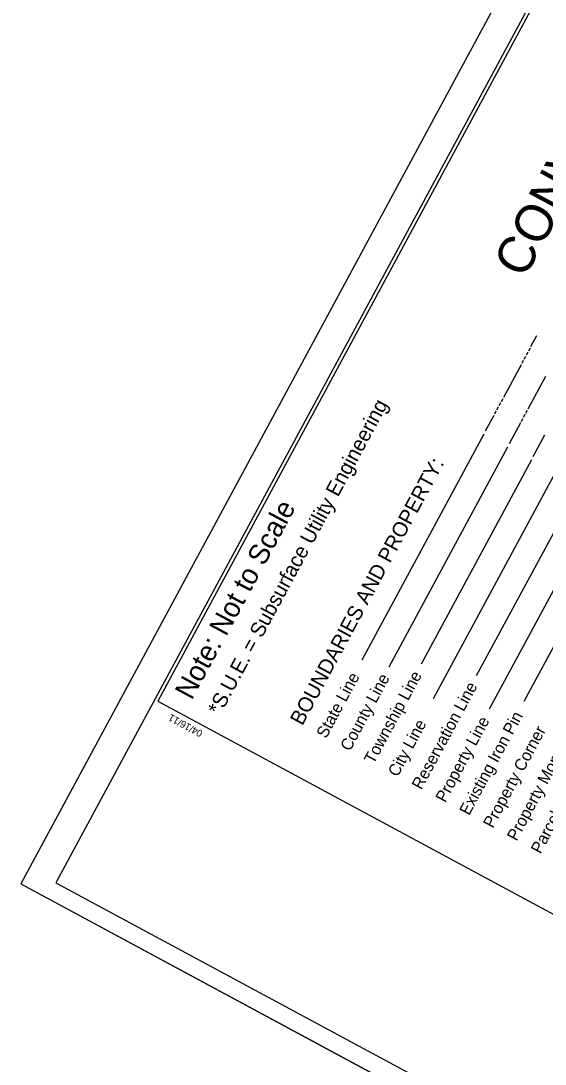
# Model space of a CAD drawing. Extents: x 1376167 to 1379209, y 761324 to 763997.
# Drawn here: x 1377442 to 1377829, y 761712 to 762484 of the extents above; entities that cross this region are included whole.
import ezdxf

# ---------------------------------------------------------------- set-up
doc = ezdxf.new("R2010")
doc.units = 0
for name, color, linetype in [('Sheet Cutting Line CELL', 7, 'Continuous'), ('Sheet Plot Border Inside CELL', 7, 'Continuous'), ('Sheet Plot Border Outside CELL', 7, 'Continuous'), ('Sheet Summary Guardrail CELL', 7, 'Continuous'), ('Sheet Symbology CELL', 7, 'Continuous')]:
    doc.layers.add(name, color=color, linetype=linetype)

msp = doc.modelspace()

# ---------------------------------------------------------------- linework, layer by layer
at = {"layer": 'Sheet Cutting Line CELL'}
for p, q in [((1378241.03, 763327.89), (1377441.9, 761845.58)), ((1377441.9, 761845.58), (1378410.15, 761323.58))]:
    msp.add_line(p, q, dxfattribs=at)
at = {"layer": 'Sheet Plot Border Inside CELL'}
msp.add_lwpolyline([(1378396.56, 761345.67), (1379187.39, 762812.58), (1378258.66, 763313.27), (1377467.83, 761846.37)], close=True, dxfattribs=at)
at = {"layer": 'Sheet Plot Border Outside CELL'}
msp.add_lwpolyline([(1378410.15, 761323.58), (1379209.29, 762805.89), (1378241.03, 763327.89), (1377441.9, 761845.58)], close=True, dxfattribs=at)
at = {"layer": 'Sheet Symbology CELL'}
for p, q in [((1377818.91, 762242.95), (1377823.33, 762251.13)), ((1377815.59, 762236.79), (1377816.78, 762238.99)), ((1377817.25, 762239.87), (1377818.44, 762242.07)), ((1377798.74, 762205.54), (1377811.79, 762229.75)), ((1377812.27, 762230.63), (1377813.45, 762232.83)), ((1377813.93, 762233.71), (1377815.12, 762235.91)), ((1377816.77, 762196.83), (1377829.82, 762221.04)), ((1377793.76, 762196.3), (1377794.95, 762198.5)), ((1377795.42, 762199.38), (1377796.61, 762201.58)), ((1377797.08, 762202.46), (1377798.27, 762204.66)), ((1377785.36, 762180.72), (1377791.63, 762192.34)), ((1377792.1, 762193.22), (1377793.29, 762195.42)), ((1377813.45, 762190.67), (1377814.63, 762192.87)), ((1377815.11, 762193.75), (1377816.3, 762195.95)), ((1377802.97, 762171.23), (1377811.31, 762186.71)), ((1377811.79, 762187.59), (1377812.97, 762189.79)), ((1377784, 762178.19), (1377693.84, 762010.95)), ((1377820.57, 762161.73), (1377829.14, 762177.62)), ((1377801.6, 762168.69), (1377713.81, 762005.85)), ((1377819.21, 762159.2), (1377737.73, 762008.07)), ((1377836.81, 762149.71), (1377746.65, 761982.48)), ((1377854.42, 762140.22), (1377778.45, 761999.32)), ((1377872.02, 762130.73), (1377787.91, 761974.72)), ((1377889.63, 762121.24), (1377813.66, 761980.34))]:
    msp.add_line(p, q, dxfattribs=at)
msp.add_lwpolyline([(1378254.97, 763301.06), (1377543.15, 761980.71), (1378466.5, 761482.92), (1379178.32, 762803.27)], close=True, dxfattribs=at)

# ---------------------------------------------------------------- texts
at = {"layer": 'Sheet Summary Guardrail CELL'}
msp.add_text('04/16/11', height=5.25, rotation=151.67024, dxfattribs=at).set_placement((1377576.79, 761958.44))
at = {"layer": 'Sheet Symbology CELL'}
for s, height, p in [('CONVENTIONAL  PLAN SHEET SYMBOLS', 27.2003, (1377814.01, 762292.51)), ('*S.U.E. = Subsurface Utility Engineering', 11, (1377589.14, 761969.63)), ('BOUNDARIES AND PROPERTY:', 11, (1377649.92, 761962.04)), ('Note: Not to Scale', 15, (1377568.17, 761980.92)), ('State Line', 8.75, (1377667.52, 761952.56)), ('County Line', 8.75, (1377685.12, 761943.07)), ('Township Line', 8.75, (1377702.73, 761933.58)), ('Reservation Line', 8.75, (1377737.93, 761914.6)), ('Parcel / Sequence Number', 8.75, (1377825.96, 761867.15)), ('City Line', 8.75, (1377720.33, 761924.09)), ('Property Line', 8.75, (1377755.54, 761905.11)), ('Existing Iron Pin', 8.75, (1377773.14, 761895.62)), ('Property Monument', 8.75, (1377808.35, 761876.64)), ('Property Corner', 8.75, (1377790.75, 761886.13))]:
    msp.add_text(s, height=height, rotation=61.67024, dxfattribs=at).set_placement(p)

doc.saveas('drawing.dxf')
